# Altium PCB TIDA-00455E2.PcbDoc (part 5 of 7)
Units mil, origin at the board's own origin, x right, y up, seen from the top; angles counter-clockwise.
Board outline 6693 x 6693.1 mil, 8 copper layers (Layer 1 - Top Layer, Layer 2 - GND, Layer 3 - Sensitive, Layer 4 - GND, Layer 5 - PWR, Layer 6 - Signal, Layer 7 - GND, Layer 8 - Bottom Layer), stack 63.122 mil thick; 537 components, 407 nets, 1686 pads, 1249 vias.
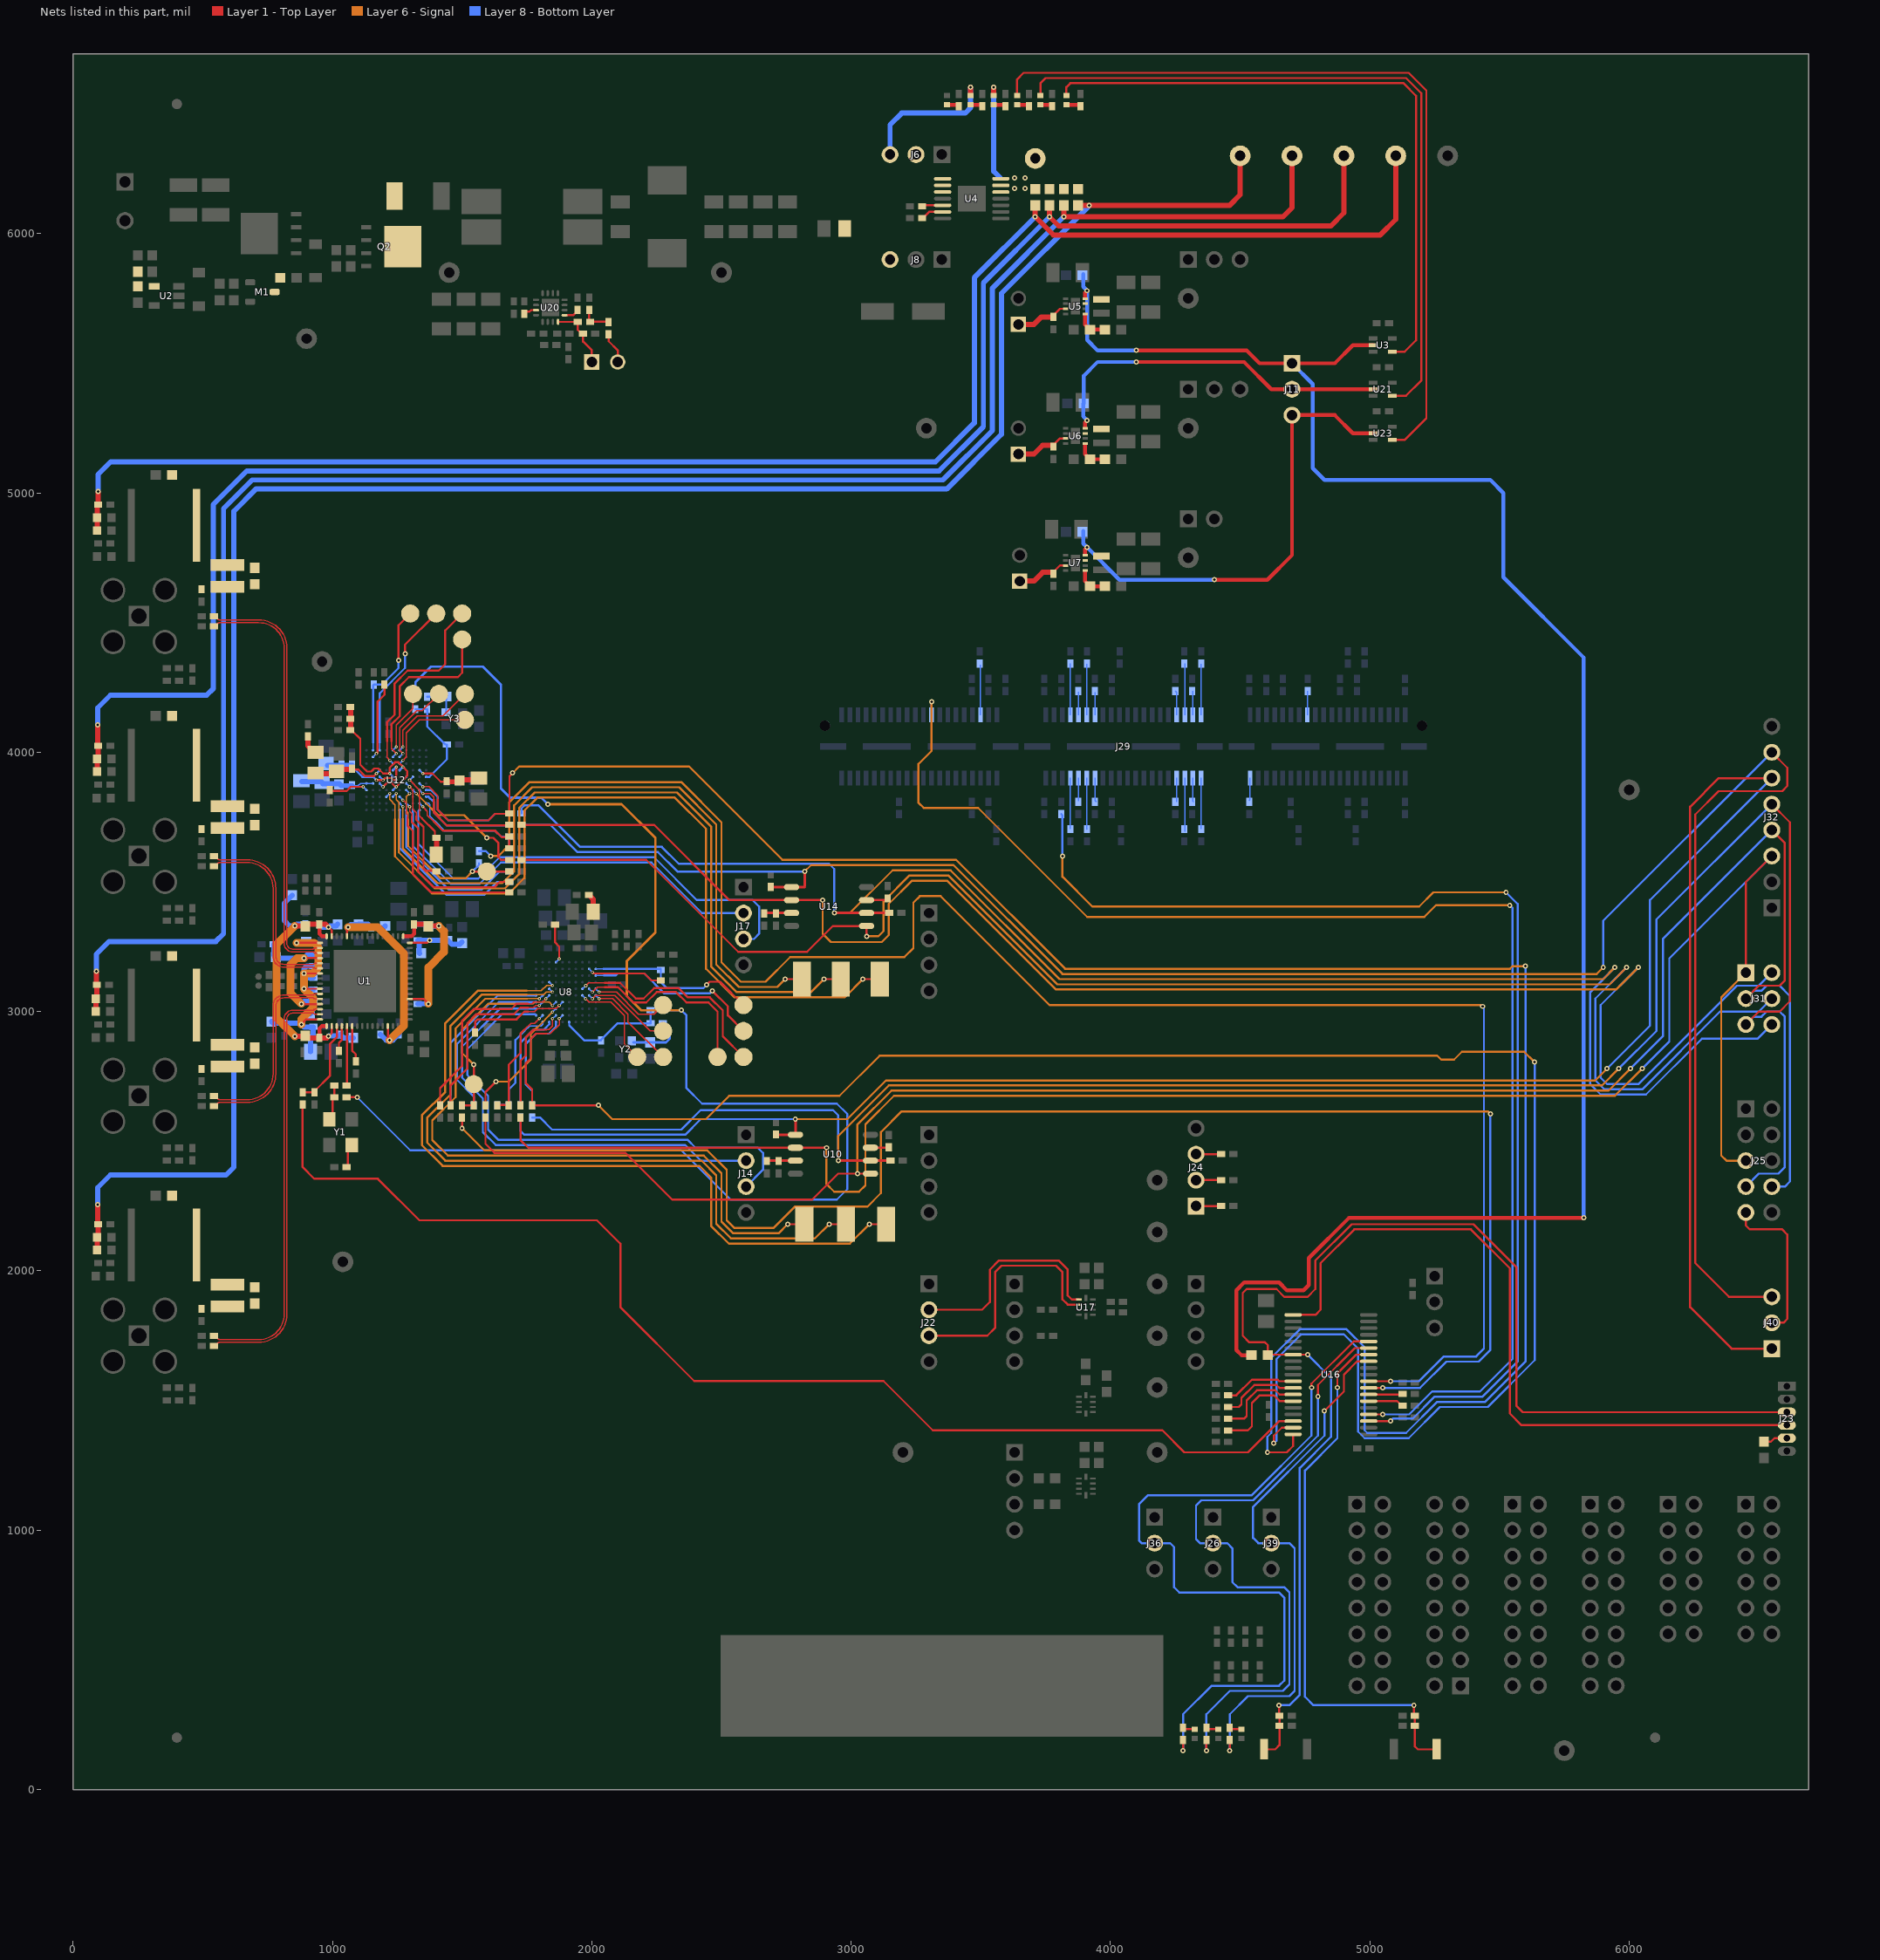
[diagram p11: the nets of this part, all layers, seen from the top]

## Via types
v1: diameter 20, hole 10, Layer 1 - Top Layer to Layer 8 - Bottom Layer, tented both sides, 1063 vias
v2: diameter 12, hole 6, Layer 1 - Top Layer to Layer 8 - Bottom Layer, tented bottom, 140 vias
v3: diameter 19.68, hole 7.87, Layer 1 - Top Layer to Layer 8 - Bottom Layer, 38 vias
v4: diameter 19.68, hole 7.87, Layer 1 - Top Layer to Layer 8 - Bottom Layer, tented top, 4 vias
v5: diameter 15.75, hole 7.87, Layer 1 - Top Layer to Layer 8 - Bottom Layer, 4 vias

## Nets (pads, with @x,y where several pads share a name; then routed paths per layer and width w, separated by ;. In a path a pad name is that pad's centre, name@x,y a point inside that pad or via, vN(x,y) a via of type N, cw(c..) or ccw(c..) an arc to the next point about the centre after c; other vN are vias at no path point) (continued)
NetC134_1: C134.1 R81.1 Y2.1 | length 215.9
  Layer 8 - Bottom Layer w10: Y2.1@2160.59,2881.5 C134.1@2225,2881.5 2286.5,2881.5 2300,2895 2300,2928.62 R81.1@2273.62,2955
NetC135_1: C135.1 C136.1 C137.1 L34.1 U12.F9 U12.F10 | length 285.8
  Layer 8 - Bottom Layer w5: C135.1@1076.24,3871.12 1098.86,3871.12 1107.44,3879.7 U12.F10@1131.08,3879.7 U12.F9@1156.67,3879.7
  Layer 8 - Bottom Layer w20: L34.1@881.24,3887.5 954.7,3887.5 963.21,3879 1026.24,3879 1034.11,3871.12 C135.1@1076.24,3871.12
NetC138_2: C138.2 C139.2 C142.2 U12.D6 U12.E8 U12.E9 U12.E10 U12.F6 | length 403.3
  Layer 1 - Top Layer w8: v2(1169.47,3892.5) v2(1195.06,3892.5) 1203.06,3900.5 1229.24,3900.5 1237.24,3892.5 v2(1246.24,3892.5) v2(1246.24,3943.68)
  Layer 8 - Bottom Layer w8: C142.2@1076.24,3948.88 1076.24,3943.76 1114.7,3905.3 U12.E10@1131.08,3905.3 U12.E9@1156.67,3905.3 v2(1169.47,3892.5) ; U12.E8@1182.26,3905.3 v2(1195.06,3892.5) ; U12.F6@1233.44,3879.7 v2(1246.24,3892.5) ; U12.D6@1233.44,3930.89 v2(1246.24,3943.68)
  Layer 8 - Bottom Layer w20: C139.2@981.4,3948.88 C142.2@1076.24,3948.88
NetC140_2: C140.2 C141.2 C162.2 U12.D5 U12.E4 U12.E6 U12.F8 U12.G6 | length 716.3
  Layer 1 - Top Layer w8: C162.2@1073.5,4082.5 1076.24,4082.5 1107.24,4051.5 1107.24,3951.5 1133.24,3925.5 1149.24,3925.5 1161.24,3937.5 1176.24,3937.5 1195.65,3918.09 v2(1220.65,3918.09) 1220.65,3940.65 1241.5,3961.5 1254.01,3961.5 v2(1271.83,3943.68) 1288.24,3927.27 1288.24,3908.91 v2(1271.83,3892.5) v2(1246.24,3866.91) 1242.83,3866.91 1226.24,3883.5 1211.65,3883.5 v2(1195.06,3866.91)
  Layer 1 - Top Layer w20: C162.2@1069.86,4086.14 C141.2@1069.86,4172.5
  Layer 8 - Bottom Layer w8: U12.F8@1182.26,3879.7 v2(1195.06,3866.91) ; v2(1220.65,3918.09) U12.E6@1233.44,3905.3 ; U12.G6@1233.44,3854.11 v2(1246.24,3866.91) ; U12.D5@1259.04,3930.89 v2(1271.83,3943.68) ; v2(1271.83,3892.5) U12.E4@1284.63,3905.3
NetC143_2: C143.2 C144.2 L35.1 U12.D8 | length 273.4
  Layer 1 - Top Layer w8: C144.2@1076.24,3933.88 1099.86,3933.88 1126.24,3907.5 1158.88,3907.5 v2(1169.47,3918.09)
  Layer 1 - Top Layer w20: L35.1@936.24,3917.5 1009.7,3917.5 1026.08,3933.88 C144.2@1076.24,3933.88
  Layer 8 - Bottom Layer w8: v2(1169.47,3918.09) U12.D8@1182.26,3930.89
NetC149_1: C149.1 L36.1 U12.E3 | length 336.7
  Layer 1 - Top Layer w5: v2(1297.42,3892.5) 1335.81,3854.11 1335.81,3754.19 1345,3745
  Layer 1 - Top Layer w8: 1345,3745 1395,3695 1395,3680.12 1402.62,3672.5 C149.1@1396.24,3672.5
  Layer 1 - Top Layer w20: L36.1@1401.24,3622.5 C149.1@1401.24,3671.12
  Layer 8 - Bottom Layer w5: v2(1297.42,3892.5) U12.E3@1310.22,3905.3
NetC150_1: C150.1 C153.2 R139.2 U12.D2 | length 250.8
  Layer 1 - Top Layer w8: v2(1348.6,3918.09) 1385.65,3918.09 1417.62,3886.12 C150.1@1441.24,3886.12
  Layer 1 - Top Layer w20: C150.1@1441.24,3886.12 1483.37,3886.12 1491.24,3894 1552.74,3894 R139.2@1561.24,3902.5
  Layer 8 - Bottom Layer w5: U12.D2@1335.81,3930.89 v2(1348.6,3918.09)
NetC154_1: C154.1 R111.1 Y3.1 | length 134.9
  Layer 8 - Bottom Layer w8: R111.1@1365,4213.62 1437.13,4213.62 C154.1@1438.5,4215 1438.5,4155.59 Y3.1@1437.52,4154.61
NetD4_1: D4.1 R168.1 | length 47.4
  Layer 1 - Top Layer w8: R168.1@4280,238.62 4285.91,232.72 D4.1@4325,232.72
NetD5_1: D5.1 R173.1 | length 47.4
  Layer 1 - Top Layer w8: R173.1@4370,238.62 4375.91,232.72 D5.1@4415,232.72
NetD6_2: D6.2 R50.2 | length 39.1
  Layer 1 - Top Layer w15: D6.2@3370,6497.28 R50.2@3409.09,6497.28
NetD7_1: D7.1 R125.2 | length 47.4
  Layer 1 - Top Layer w15: D7.1@3460,6497.28 3499.09,6497.28 R125.2@3505,6491.38
NetD8_2: D8.2 R127.1 | length 47.4
  Layer 1 - Top Layer w15: D8.2@3550,6497.28 3589.09,6497.28 R127.1@3595,6491.38
NetD9_1: D9.1 U3.4 | length 2459
  Layer 1 - Top Layer w8: D9.1@3830,6532.72 3830,6565 3845,6580 5130,6580 5178,6532 5178,5588 5134.41,5544.41 U3.4@5087.4,5544.41
NetD9_2: D9.2 R130.1 | length 57.4
  Layer 1 - Top Layer w15: D9.2@3830,6497.28 3879.09,6497.28 R130.1@3885,6491.38
NetD10_1: D10.1 U21.4 | length 2791.5
  Layer 1 - Top Layer w8: D10.1@3730,6532.72 3730,6580 3750,6600 5140,6600 5198,6542 5198,5433 5139.41,5374.41 U21.4@5087.4,5374.41
NetD10_2: D10.2 R131.2 | length 47.4
  Layer 1 - Top Layer w15: D10.2@3730,6497.28 3769.09,6497.28 R131.2@3775,6491.38
NetD11_1: D11.1 R132.2 | length 47.4
  Layer 1 - Top Layer w15: D11.1@3640,6497.28 3679.09,6497.28 R132.2@3685,6491.38
NetD11_2: D11.2 U23.4 | length 3108
  Layer 1 - Top Layer w8: D11.2@3640,6532.72 3640,6595 3665,6620 5150,6620 5218,6552 5218,5288 5134.41,5204.41 U23.4@5087.4,5204.41
NetD12_2: D12.2 R118.1 | length 47.4
  Layer 1 - Top Layer w8: R118.1@4460,238.62 4465.91,232.72 D12.2@4505,232.72
NetJ6_2: J6.2 U4.8 U4.9 U4.10
NetJ9_1: J9.1 R129.2 U5.3 | length 206.3
  Layer 1 - Top Layer w8: R129.2@3780,5683.62 3780,5685 3805.16,5710.16 U5.3@3827.6,5710.16
  Layer 1 - Top Layer w20: J9.1@3645,5650 3705,5650 3733.62,5678.62 R129.2@3780,5678.62
NetJ13_1: J13.1 R30.1 R31.1 U20.8 | length 257.8
  Layer 1 - Top Layer w8: U20.8@1869.53,5659.88 1946.26,5659.88 R30.1@1946.38,5660 1946.38,5628.62 1960,5615 R31.1@1966.38,5615 1966.38,5583.62 2000,5550 J13.1@2000,5505
NetJ13_2: J13.2 R117.1 | length 120.9
  Layer 1 - Top Layer w8: R117.1@2065,5611.38 2065,5585 2100,5550 J13.2@2100,5505
NetJ14_2: J14.2 U8.K3 | length 1769
  Layer 8 - Bottom Layer w8: U8.K3@1784.84,3011.02 1646.02,3011.02 1500,2865 1500,2745 1580,2665 1580,2535 1630,2485 2360,2485 2420,2425 J14.2@2595,2425
NetJ14_3: J14.3 U8.K2 | length 1920
  Layer 8 - Bottom Layer w8: U8.K2@1784.84,2985.43 1780.28,2990 1655,2990 1520,2855 1520,2755 1600,2675 1600,2545 1640,2505 2370,2505 2400,2475 2640,2475 2660,2455 2660,2390 J14.3@2595,2325
NetJ15_1: J15.1 R204.2 U7.3 | length 208.3
  Layer 1 - Top Layer w8: R204.2@3780,4693.62 3780,4695 3805.16,4720.16 U7.3@3827.6,4720.16
  Layer 1 - Top Layer w20: J15.1@3645,4660 J15.1@3650,4660 3705,4660 3738.62,4693.62 R204.2@3780,4693.62
NetJ17_2: J17.2 U12.K3 | length 1589
  Layer 8 - Bottom Layer w8: U12.K3@1310.22,3777.34 1310.22,3638.52 1456.24,3492.5 1567.5,3492.5 1650,3575 2230,3575 2425,3380 J17.2@2585,3380
NetJ17_3: J17.3 U12.K2 | length 1787.6
  Layer 8 - Bottom Layer w8: U12.K2@1335.81,3777.34 1331.24,3772.78 1331.24,3647.5 1466.24,3512.5 1562.5,3512.5 1645,3595 2240,3595 2405,3430 2620,3430 2645,3405 2645,3300 2625,3280 J17.3@2585,3280
NetJ22_2: J22.2 U17.1 | length 851.3
  Layer 1 - Top Layer w8: J22.2@3300,1850 3505,1850 3535,1880 3535,2005 3570,2040 3800,2040 3835,2005 3835,1905 3850.47,1889.53 U17.1@3878.43,1889.53
NetJ22_3: J22.3 U17.2 | length 939.9
  Layer 1 - Top Layer w8: J22.3@3300,1750 3525,1750 3555,1780 3555,1995 3580,2020 3790,2020 3815,1995 3815,1890 3835.16,1869.84 U17.2@3878.43,1869.84
NetJ23_5: J23.5 R142.1 | length 95.6
  Layer 1 - Top Layer w8: R142.1@6520,1341.5 6546.5,1341.5 6560,1355 J23.5@6608,1355 J23.5@6610,1355
NetJ24_1: J24.1 R143.2 | length 96.4
  Layer 1 - Top Layer w8: J24.1@4330,2250 R143.2@4426.38,2250
NetJ24_2: J24.2 R145.2 | length 96.4
  Layer 1 - Top Layer w8: J24.2@4330,2350 R145.2@4426.38,2350
NetJ24_3: J24.3 R147.2 | length 96.4
  Layer 1 - Top Layer w8: J24.3@4330,2450 R147.2@4426.38,2450
NetJ25_9: J25.9 J40.2 | length 615.7
  Layer 1 - Top Layer w8: J25.9@6450,2225 6450,2175 6465,2160 6590,2160 6610,2140 6610,1815 6595,1800 J40.2@6550,1800
NetJ30_1: J30.1 R201.2 U6.3 | length 208.3
  Layer 1 - Top Layer w8: R201.2@3780,5183.62 3780,5185 3805.16,5210.16 U6.3@3827.6,5210.16
  Layer 1 - Top Layer w20: J30.1@3645,5150 3705,5150 3738.62,5183.62 R201.2@3780,5183.62
NetL3_1: L3.1 L7.2 R1.1
NetL3_2: L3.2 L4.1 R1.2 R2.1
NetL5_1: L5.1 L8.2 R3.1
NetL5_2: L5.2 L6.1 R3.2 R4.1
NetL11_1: L11.1 L15.2 R9.1
NetL11_2: L11.2 L12.1 R9.2 R10.1
NetL13_1: L13.1 L16.2 R11.1
NetL13_2: L13.2 L14.1 R11.2 R12.1
NetL18_1: L18.1 U5.7
NetL19_1: L19.1 U6.7
NetL20_1: L20.1 U7.7
NetL32_2: L32.2 R78.2 | length 71.8
  Layer 1 - Top Layer w20: R78.2@1988.62,3450 2005,3433.62 L32.2@2005,3385
NetL35_2: L35.2 R108.2 | length 76.7
  Layer 1 - Top Layer w20: R108.2@905,4061.38 905,4025 930,4000 L35.2@935,4000
NetM1_3: M1.3 R19.1
NetQ2_5: Q2.5 R17.1
NetR21_1: R21.1 R23.2 U2.4
NetR26_2: R26.2 U20.3 | length 50.6
  Layer 1 - Top Layer w8: R26.2@1740,5691.38 1747.62,5699 1760,5699 1766.16,5705.16 U20.3@1784.88,5705.16
NetR28_2: R28.2 U20.9 | length 61.1
  Layer 1 - Top Layer w8: U20.9@1895.12,5685.47 1928.47,5685.47 1945,5702 R28.2@1945,5706.38
NetR29_2: R29.2 R30.2 R117.2 | length 119.8
  Layer 1 - Top Layer w8: R29.2@1990,5706.38 1990,5663.62 R30.2@1993.62,5660 2063.62,5660 R117.2@2065,5658.62
NetR37_1: R37.1 R38.2 U5.5 | length 121.9
  Layer 1 - Top Layer w15: U5.5@3902.4,5687 3902.4,5649.09 R38.2@3921.5,5630 R37.1@3978.5,5630
NetR40_1: R40.1 R41.2 U6.5 | length 121.9
  Layer 1 - Top Layer w15: U6.5@3902.4,5187 3902.4,5149.09 R41.2@3921.5,5130 R40.1@3978.5,5130
NetR43_1: R43.1 R44.2 U7.5 | length 121.9
  Layer 1 - Top Layer w15: U7.5@3902.4,4697 3902.4,4659.09 R44.2@3921.5,4640 R43.1@3978.5,4640
NetR45_2: R45.2 Y1.1 | length 93.2
  Layer 1 - Top Layer w8: R45.2@1054.82,2400 1060,2405.18 1060,2470.49 Y1.1@1074.51,2485
NetR46_1: R46.1 R47.2 Y1.3 | length 138.2
  Layer 1 - Top Layer w8: Y1.3@987.89,2585 1000,2597.11 1000,2662.42 R46.1@1007.58,2670 R47.2@1007.58,2715
NetR47_1: R47.1 U1.5 | length 229.8
  Layer 1 - Top Layer w8: R47.1@1054.82,2715 1056.1,2716.28 U1.5@1056.1,2944.27
NetR52_1: R52.1 U1.6 | length 141.5
  Layer 1 - Top Layer w8: U1.6@1075.79,2944.27 1075.79,2849.21 1090,2835 R52.1@1090,2808.62
NetR54_2: R54.2 U1.4 | length 100.4
  Layer 1 - Top Layer w8: R54.2@1025,2848.62 1025,2880 1036.42,2891.42 U1.4@1036.42,2944.27
NetR58_1: R58.1 TP37.1 U8.A9 | length 673.6
  Layer 1 - Top Layer w8: v1(2442.5,3102.5) 2455,3115 2495,3115 TP37.1@2585,3025
  Layer 8 - Bottom Layer w5: U8.A9@2015.16,3164.57 2045,3164.57
  Layer 8 - Bottom Layer w8: 2045,3164.57 R58.1@2266.38,3164.57 ; R58.1@2266.38,3160 2266.38,3113.62 2290,3090 2430,3090 v1(2442.5,3102.5)
NetR60_1: R60.1 R62.2 U10.3 | length 110.3
  Layer 1 - Top Layer w10: R62.2@2675,2425 U10.3@2785.31,2425
NetR61_2: R61.2 U10.7 | length 70.3
  Layer 1 - Top Layer w10: U10.7@3074.68,2475 R61.2@3145,2475
NetR65_1: R65.1 U8.J4 | length 669.6
  Layer 1 - Top Layer w5: 1755,3015 1775,3015 1783.82,3023.82 v2(1797.64,3023.82)
  Layer 1 - Top Layer w8: R65.1@1460,2638.62 1455,2643.62 1455,2715 1520,2780 1520,2955 1555,2990 1700,2990 1725,3015 1755,3015
  Layer 8 - Bottom Layer w5: v2(1797.64,3023.82) U8.J4@1810.43,3036.61
NetR66_1: R66.1 U8.H5 | length 739.9
  Layer 1 - Top Layer w5: 1755,3030 1770,3030 1776.61,3036.61 1810.43,3036.61 v2(1823.23,3049.41)
  Layer 1 - Top Layer w8: R66.1@1420,2638.62 1415,2643.62 1415,2705 1500,2790 1500,2965 1545,3010 1690,3010 1710,3030 1755,3030
  Layer 8 - Bottom Layer w5: v2(1823.23,3049.41) U8.H5@1836.02,3062.2
NetR67_1: R67.1 U8.K5 | length 648.7
  Layer 8 - Bottom Layer w8: R67.1@1455,2636.65 R67.1@1455,2638.62 1455,2880 1637.2,3062.2 U8.K5@1784.84,3062.2
NetR69_2: R69.2 U8.G2 | length 438.5
  Layer 1 - Top Layer w5: 1825,2930 1835,2930 1848.82,2943.82 v2(1848.82,2972.64)
  Layer 1 - Top Layer w8: R69.2@1725,2638.62 1725,2810 1745,2830 1745,2900 1775,2930 1825,2930
  Layer 8 - Bottom Layer w5: v2(1848.82,2972.64) U8.G2@1861.61,2985.43
NetR70_2: R70.2 U8.G3 | length 514.2
  Layer 1 - Top Layer w8: R70.2@1590,2638.62 1590,2690 v1(1630,2730)
  Layer 6 - Signal w5: 1790.59,2940 v2(1848.82,2998.23)
  Layer 6 - Signal w8: v1(1630,2730) 1680,2730 1765,2815 1765,2914.41 1790.59,2940
  Layer 8 - Bottom Layer w5: v2(1848.82,2998.23) U8.G3@1861.61,3011.02
NetR71_2: R71.2 U8.G1 | length 409.2
  Layer 8 - Bottom Layer w8: R71.2@1770,2638.62 1770,2695 1745,2720 1745,2875 1785,2915 1835,2915 1861.61,2941.61 U8.G1@1861.61,2959.84
NetR72_1: R72.1 U8.B9 | length 295.3
  Layer 1 - Top Layer w8: v2(2002.36,3151.77) 2007.13,3147 2203,3147 2230,3120 R72.1@2266.38,3120
  Layer 8 - Bottom Layer w5: U8.B9@1989.57,3164.57 v2(2002.36,3151.77)
NetR73_2: R73.2 U8.H1 | length 390.6
  Layer 8 - Bottom Layer w8: R73.2@1725,2638.62 1725,2880 1775,2930 1815,2930 1836.02,2951.02 U8.H1@1836.02,2959.84
NetR74_1: R74.1 U12.B9 | length 295.3
  Layer 1 - Top Layer w8: v2(1169.47,3994.86) 1174.24,3999.63 1174.24,4195.5 1201.24,4222.5 R74.1@1201.24,4258.88
  Layer 8 - Bottom Layer w5: U12.B9@1156.67,3982.07 v2(1169.47,3994.86)
NetR75_2: R75.2 U8.K4 | length 635.1
  Layer 8 - Bottom Layer w8: R75.2@1545,2638.62 1545,2672.38 1480,2737.38 1480,2875 1641.61,3036.61 U8.K4@1784.84,3036.61
NetR76_2: R76.2 U8.G10 | length 156.7
  Layer 1 - Top Layer w8: R76.2@1858.62,3335 1858.62,3266.38 1874.41,3250.59 v2(1874.41,3202.95)
  Layer 8 - Bottom Layer w5: U8.G10@1861.61,3190.16 v2(1874.41,3202.95)
NetR77_1: R77.1 U8.F4 | length 410.3
  Layer 1 - Top Layer w5: 1755,3000 1780,3000 1791.02,3011.02 1861.61,3011.02 v2(1874.41,3023.82)
  Layer 1 - Top Layer w8: R77.1@1550,2918.62 1550,2960 1560,2970 1710,2970 1740,3000 1755,3000
  Layer 8 - Bottom Layer w5: v2(1874.41,3023.82) U8.F4@1887.2,3036.61
NetR88_1: R88.1 TP47.1 U12.A9 | length 601.2
  Layer 1 - Top Layer w8: v1(1255,4355) 1255,4490 TP47.1@1300,4535
  Layer 8 - Bottom Layer w5: U12.A9@1156.67,4007.66 1156.67,4037.5
  Layer 8 - Bottom Layer w8: 1156.67,4037.5 R88.1@1156.67,4258.88 ; R88.1@1160,4261.38 1191.38,4261.38 1255,4325 v1(1255,4355)
NetR90_1: R90.1 R92.2 U14.3 | length 105.3
  Layer 1 - Top Layer w10: R92.2@2665,3380 U14.3@2770.32,3380
NetR91_2: R91.2 U14.7 | length 83
  Layer 1 - Top Layer w8: U14.7@3059.69,3430 3133.62,3430 R91.2@3140,3436.38
NetR95_1: R95.1 U12.J4 | length 666.2
  Layer 1 - Top Layer w5: v2(1297.42,3790.14) 1297.42,3771.58 1306,3763 1306,3752
  Layer 1 - Top Layer w8: 1306,3752 1306,3731 1330,3707 1330,3540 1390,3480 1625,3480 1645,3500 R95.1@1681.38,3500
  Layer 8 - Bottom Layer w5: U12.J4@1284.63,3802.93 v2(1297.42,3790.14)
NetR96_1: R96.1 U12.H5 | length 720
  Layer 1 - Top Layer w5: v2(1271.83,3815.73) 1284.63,3802.93 1284.63,3763.37 1289,3759 1289,3750
  Layer 1 - Top Layer w8: 1289,3750 1289,3718 1310,3697 1310,3530 1380,3460 R96.1@1681.38,3460
  Layer 8 - Bottom Layer w5: U12.H5@1259.04,3828.52 v2(1271.83,3815.73)
NetR97_1: R97.1 U12.K5 | length 664.4
  Layer 8 - Bottom Layer w8: U12.K5@1259.04,3777.34 1259.04,3630.96 1440,3450 1585,3450 1635,3500 R97.1@1681.38,3500
NetR99_2: R99.2 U12.G2 | length 438.5
  Layer 1 - Top Layer w5: v2(1348.6,3841.32) 1377.42,3841.32 1391.24,3827.5 1391.24,3817.5
  Layer 1 - Top Layer w8: 1391.24,3817.5 1391.24,3767.5 1441.24,3717.5 R99.2@1682.62,3717.5
  Layer 8 - Bottom Layer w5: U12.G2@1335.81,3854.11 v2(1348.6,3841.32)
NetR100_2: R100.2 U12.G3 | length 514.9
  Layer 1 - Top Layer w8: v1(1595,3670) 1620,3670 1640,3650 1640,3595 1650,3585 R100.2@1681.38,3585
  Layer 6 - Signal w5: v2(1323.01,3841.32) 1381.24,3783.09
  Layer 6 - Signal w8: 1381.24,3783.09 1406.83,3757.5 1507.5,3757.5 v1(1595,3670)
  Layer 8 - Bottom Layer w5: U12.G3@1310.22,3854.11 v2(1323.01,3841.32)
NetR101_2: R101.2 U12.G1 | length 409.2
  Layer 8 - Bottom Layer w8: U12.G1@1361.4,3854.11 1379.63,3854.11 1406.24,3827.5 1406.24,3777.5 1446.24,3737.5 1601.24,3737.5 1626.24,3762.5 R101.2@1682.62,3762.5
NetR103_2: R103.2 U12.H1 | length 390.6
  Layer 8 - Bottom Layer w8: U12.H1@1361.4,3828.52 1370.22,3828.52 1391.24,3807.5 1391.24,3767.5 1441.24,3717.5 R103.2@1682.62,3717.5
NetR105_2: R105.2 U12.K4 | length 637
  Layer 8 - Bottom Layer w8: U12.K4@1284.63,3777.34 1284.63,3634.11 1448.74,3470 1575,3470 1645,3540 R105.2@1681.38,3540
NetR106_2: R106.2 U12.G10 | length 150.4
  Layer 1 - Top Layer w8: R106.2@992.5,3851.12 1054.86,3851.12 1070.65,3866.91 v2(1118.29,3866.91)
  Layer 8 - Bottom Layer w5: v2(1118.29,3866.91) U12.G10@1131.08,3854.11
NetR107_1: R107.1 U12.F4 | length 410.3
  Layer 1 - Top Layer w5: v2(1297.42,3866.91) 1310.22,3854.11 1310.22,3779.78 1323,3767 1323,3754
  Layer 1 - Top Layer w8: 1323,3754 1323,3740 1351.24,3711.76 1351.24,3552.5 1361.24,3542.5 R107.1@1402.62,3542.5
  Layer 8 - Bottom Layer w5: U12.F4@1284.63,3879.7 v2(1297.42,3866.91)
NetR126_2: R126.2 U16.12 | length 305.2
  Layer 1 - Top Layer w8: R126.2@4453.62,1475 4495,1475 4505,1485 4505,1510 4555,1560 4640,1560 4651.18,1548.82 U16.12@4704.33,1548.82
NetR128_2: R128.2 U16.13 | length 338.4
  Layer 1 - Top Layer w8: R128.2@4453.62,1430 4515,1430 4525,1440 4525,1500 4565,1540 4635,1540 4651.77,1523.23 U16.13@4704.33,1523.23
NetR134_2: R134.2 R159.1 TP41.1 U8.G4 | length 771.4
  Layer 1 - Top Layer w8: R159.1@1500,2638.62 R134.2@1545,2638.62 TP41.1@1545,2720 v1(1545,2795)
  Layer 6 - Signal w5: 1750,3030 1775,3030 1781.61,3036.61 1836.02,3036.61 v2(1848.82,3023.82)
  Layer 6 - Signal w8: v1(1545,2795) 1500,2840 1500,2930 1600,3030 1750,3030
  Layer 8 - Bottom Layer w5: v2(1848.82,3023.82) U8.G4@1861.61,3036.61
NetR138_2: R138.2 R162.1 TP42.1 U12.G4 | length 722.2
  Layer 1 - Top Layer w8: v1(1540,3540) TP42.1@1595,3540 R138.2@1681.38,3540
  Layer 6 - Signal w5: 1291.24,3742.5 1291.24,3767.5 1284.63,3774.11 1284.63,3828.52 v2(1297.42,3841.32)
  Layer 6 - Signal w8: 1291.24,3742.5 1291.24,3638.76 1415,3515 1515,3515 v1(1540,3540)
  Layer 8 - Bottom Layer w5: U12.G4@1284.63,3854.11 v2(1297.42,3841.32)
  Layer 8 - Bottom Layer w8: v1(1540,3540) 1565,3565 R162.1@1565,3571.38
NetR140_2: R140.2 U4.13 | length 89
  Layer 1 - Top Layer w8: R140.2@3273.62,6060 3277,6060 3300.82,6083.82 U4.13@3352.8,6083.82
NetR154_1: R154.1 R155.2 U1.3 | length 336.6
  Layer 1 - Top Layer w8: R154.1@885,2688.62 R155.2@930,2688.62 930,2692 990,2752 990,2875 1016.73,2901.73 U1.3@1016.73,2944.27
NetR163_2: R163.2 U16.11 | length 277.9
  Layer 1 - Top Layer w8: R163.2@4453.62,1520 4485,1520 4545,1580 4645,1580 4650.59,1574.41 U16.11@4704.33,1574.41
NetR164_2: R164.2 U16.14 | length 370.6
  Layer 1 - Top Layer w8: R164.2@4451.65,1385 R164.2@4453.62,1385 4530,1385 4545,1400 4545,1490 4575,1520 4630,1520 4652.36,1497.64 U16.14@4704.33,1497.64
NetR165_2: R165.2 U16.25 | length 138
  Layer 1 - Top Layer w8: U16.25@4995.67,1497.64 5105.36,1497.64 5123,1480 R165.2@5126.38,1480
NetR166_2: R166.2 U16.26 | length 131.4
  Layer 1 - Top Layer w8: U16.26@4995.67,1523.23 5124.61,1523.23 R166.2@5126.38,1525
NetR184_1: R184.1 U4.12 | length 81
  Layer 1 - Top Layer w8: R184.1@3273.62,6105 3278.03,6109.41 U4.12@3352.8,6109.41
NetTP18_1: TP18.1 U8.H7 | length 3087.3
  Layer 1 - Top Layer w8: v1(3070,2180) TP18.1@3135,2180
  Layer 6 - Signal w5: 1750,3080 1805,3080 1825.59,3100.59 v2(1848.82,3100.59)
  Layer 6 - Signal w8: 1750,3080 1560,3080 1435,2955 1435,2690 1345,2600 1345,2485 1425,2405 2415,2405 2460,2360 2460,2173.43 2528.43,2105 2995,2105 v1(3070,2180)
  Layer 8 - Bottom Layer w5: U8.H7@1836.02,3113.39 v2(1848.82,3100.59)
NetTP19_1: TP19.1 U8.H6 | length 2853.4
  Layer 1 - Top Layer w8: v1(2915,2180) TP19.1@2980,2180
  Layer 6 - Signal w5: 1750,3065 1815,3065 1825,3075 v2(1848.82,3075)
  Layer 6 - Signal w8: 1750,3065 1575,3065 1455,2945 1455,2680 1365,2590 1365,2495 1435,2425 2423.28,2425 2480,2368.28 2480,2181.72 2536.72,2125 2860,2125 v1(2915,2180)
  Layer 8 - Bottom Layer w5: U8.H6@1836.02,3087.8 v2(1848.82,3075)
NetTP20_1: TP20.1 U8.J5 | length 2563.3
  Layer 1 - Top Layer w8: v1(2755,2180) TP20.1@2820,2180
  Layer 6 - Signal w5: 1750.59,3049.41 v2(1797.64,3049.41)
  Layer 6 - Signal w8: 1750.59,3049.41 1589.41,3049.41 1475,2935 1475,2670 1385,2580 1385,2505 1445,2445 2431.57,2445 2500,2376.57 2500,2190 2545,2145 2720,2145 v1(2755,2180)
  Layer 8 - Bottom Layer w5: v2(1797.64,3049.41) U8.J5@1810.43,3062.2
NetTP21_1: TP21.1 U12.H7 | length 3167.2
  Layer 1 - Top Layer w8: v1(3045,3125) TP21.1@3110,3125
  Layer 6 - Signal w5: v2(1220.65,3841.32) 1220.65,3818.09 1241.24,3797.5 1241.24,3742.5
  Layer 6 - Signal w8: 1241.24,3742.5 1241.24,3598.76 1385,3455 1680,3455 1740,3515 1740,3775 1790,3825 2320,3825 2440,3705 2440,3165.15 2550.15,3055 2975,3055 v1(3045,3125)
  Layer 8 - Bottom Layer w5: U12.H7@1207.85,3828.52 v2(1220.65,3841.32)
NetTP22_1: TP22.1 U12.H6 | length 2969.6
  Layer 1 - Top Layer w8: v1(2895,3125) TP22.1@2960,3125
  Layer 6 - Signal w5: v2(1246.24,3841.32) 1246.24,3817.5 1256.24,3807.5 1256.24,3742.5
  Layer 6 - Signal w8: 1256.24,3742.5 1256.24,3613.76 1395,3475 1665,3475 1720,3530 1720,3785 1780,3845 2328.28,3845 2460,3713.28 2460,3173.43 2558.43,3075 2845,3075 v1(2895,3125)
  Layer 8 - Bottom Layer w5: U12.H6@1233.44,3828.52 v2(1246.24,3841.32)
NetTP23_1: TP23.1 U12.J5 | length 2723.6
  Layer 1 - Top Layer w8: v1(2745,3125) TP23.1@2810,3125
  Layer 6 - Signal w5: 1271.83,3743.09 v2(1271.83,3790.14)
  Layer 6 - Signal w8: 1271.83,3743.09 1271.83,3628.17 1405,3495 1655,3495 1700,3540 1700,3795 1770,3865 2336.57,3865 2480,3721.57 2480,3181.72 2566.72,3095 2715,3095 v1(2745,3125)
  Layer 8 - Bottom Layer w5: U12.J5@1259.04,3802.93 v2(1271.83,3790.14)
NetTP29_1: TP29.1 U12.A6 | length 249.3
  Layer 1 - Top Layer w5: v2(1246.24,4020.45) 1246.24,4104.33 1310.5,4168.59 TP29.1@1310.5,4225
  Layer 8 - Bottom Layer w5: U12.A6@1233.44,4007.66 v2(1246.24,4020.45)
NetTP30_1: TP30.1 U12.B5 | length 328.3
  Layer 1 - Top Layer w5: v2(1271.83,3994.86) 1259,4007.69 1259,4094 1325,4160 1345.5,4160 TP30.1@1410.5,4225
  Layer 8 - Bottom Layer w5: U12.B5@1259.04,3982.07 v2(1271.83,3994.86)
NetTP31_1: TP31.1 U12.A5 | length 378.9
  Layer 1 - Top Layer w5: v2(1271.83,4020.45) 1271.83,4084.33 1327.5,4140 1425.5,4140 TP31.1@1510.5,4225
  Layer 8 - Bottom Layer w5: U12.A5@1259.04,4007.66 v2(1271.83,4020.45)
NetTP32_1: TP32.1 U12.C5 | length 375.5
  Layer 1 - Top Layer w5: v2(1271.83,3969.27) 1284.7,3982.14 1284.7,4074.7 1335,4125 TP32.1@1510.5,4125
  Layer 8 - Bottom Layer w5: U12.C5@1259.04,3956.48 v2(1271.83,3969.27)
NetTP33_1: TP33.1 U8.A6 | length 314.8
  Layer 1 - Top Layer w5: v2(2027.95,3075) 2095,3075 2180,2990 2240,2990 TP33.1@2275,3025
  Layer 8 - Bottom Layer w5: U8.A6@2015.16,3087.8 v2(2027.95,3075)
NetTP34_1: TP34.1 U8.B5 | length 352.6
  Layer 1 - Top Layer w5: v2(2002.36,3049.41) 2014.86,3061.91 2088.09,3061.91 2225,2925 TP34.1@2275,2925
  Layer 8 - Bottom Layer w5: U8.B5@1989.57,3062.2 v2(2002.36,3049.41)
NetTP35_1: TP35.1 U8.A5 | length 375.7
  Layer 1 - Top Layer w5: v2(2027.95,3049.41) 2080.59,3049.41 2140,2990 2140,2960 TP35.1@2275,2825
  Layer 8 - Bottom Layer w5: U8.A5@2015.16,3062.2 v2(2027.95,3049.41)
NetTP36_1: TP36.1 U8.C5 | length 373.7
  Layer 1 - Top Layer w5: v2(1976.77,3049.41) 1989.27,3036.91 2073.09,3036.91 2125,2985 2125,2875 TP36.1@2175,2825
  Layer 8 - Bottom Layer w5: U8.C5@1963.98,3062.2 v2(1976.77,3049.41)
NetTP38_1: TP38.1 U8.A8 | length 693.9
  Layer 1 - Top Layer w8: v1(2465,3080) 2525,3020 2525,2985 TP38.1@2585,2925
  Layer 8 - Bottom Layer w5: U8.A8@2015.16,3138.98 2046.61,3138.98
  Layer 8 - Bottom Layer w8: 2046.61,3138.98 2091.98,3138.98 2100,3147 2203,3147 2280,3070 2455,3070 v1(2465,3080)
NetTP39_1: TP39.1 U8.B6 | length 755.7
  Layer 1 - Top Layer w5: v2(2002.36,3075) 2021.36,3094 2050.26,3094
  Layer 1 - Top Layer w8: 2050.26,3094 2101,3094 2160,3035 2210,3035 2250,3075 2325,3075 2365,3035 2450,3035 2485,3000 TP39.1@2485,2825
  Layer 8 - Bottom Layer w5: U8.B6@1989.57,3087.8 v2(2002.36,3075)
NetTP40_1: TP40.1 U8.C6 | length 841.1
  Layer 1 - Top Layer w5: v2(1976.8,3099.8) 1988,3111 2050,3111
  Layer 1 - Top Layer w8: 2050,3111 2109,3111 2170,3050 2200,3050 2240,3090 2335,3090 2370,3055 2455,3055 2505,3005 2505,2905 TP40.1@2585,2825
  Layer 8 - Bottom Layer w5: U8.C6@1964,3087 v2(1976.8,3099.8)
NetTP48_1: TP48.1 U12.A8 | length 617.5
  Layer 1 - Top Layer w8: v1(1280,4380) 1280,4415 TP48.1@1400,4535
  Layer 8 - Bottom Layer w5: U12.A8@1182.26,4007.66 1182.26,4037.5
  Layer 8 - Bottom Layer w8: 1182.26,4037.5 1182.26,4227.26 1280,4325 v1(1280,4380)
NetTP49_1: TP49.1 U12.B6 | length 689.6
  Layer 1 - Top Layer w5: 1227.24,4042.76 1227.24,4013.86 v2(1246.24,3994.86)
  Layer 1 - Top Layer w8: 1227.24,4042.76 1227.24,4107.24 1260,4140 1260,4255 1295,4290 1483.62,4290 1500,4306.38 TP49.1@1500,4435
  Layer 8 - Bottom Layer w5: U12.B6@1233.44,3982.07 v2(1246.24,3994.86)
NetTP50_1: TP50.1 U12.C6 | length 778.8
  Layer 1 - Top Layer w5: 1210.24,4042.5 1210.24,3980.5 v2(1221.44,3969.3)
  Layer 1 - Top Layer w8: 1210.24,4042.5 1210.24,4115.24 1240,4145 1240,4265 1290,4315 1410,4315 1435,4340 1435,4470 TP50.1@1500,4535
  Layer 8 - Bottom Layer w5: v2(1221.44,3969.3) U12.C6@1234.24,3956.5
NRESET_OV1: R159.2 U16.27 | length 6048.2
  Layer 1 - Top Layer w8: v1(1500,2550) R159.2@1500,2591.38 ; U16.27@4995.67,1548.82 v1(5050,1548.82)
  Layer 6 - Signal w8: v1(1500,2550) 1585,2465 2445,2465 2520,2390 2520,2195 2550,2165 2700,2165 2782.5,2247.5 3062.5,2247.5 3115,2300 3115,2535 3195,2615 5455,2615 v1(5465,2605)
  Layer 8 - Bottom Layer w8: v1(5050,1548.82) 5193.82,1548.82 5295,1650 5420,1650 5465,1695 v1(5465,2605)
NRESET_OV2: R162.2 U16.28 | length 6961.3
  Layer 1 - Top Layer w8: U16.28@4995.67,1574.41 v1(5080,1574.41)
  Layer 6 - Signal w8: v1(1610,3600) 1640,3600 1681.24,3641.24 1681.24,3806.24 1760,3885 2344.85,3885 2500,3729.85 2500,3190 2575,3115 2670,3115 2765,3210 3205,3210 3240,3245 3240,3420 3265,3445 3345,3445 3765,3025 5430,3025 v1(5435,3020)
  Layer 8 - Bottom Layer w8: R162.2@1565,3618.62 1591.38,3618.62 v1(1610,3600) ; v1(5080,1574.41) 5189.41,1574.41 5285,1670 5410,1670 5440,1700 5440,3015 v1(5435,3020)
NRESET_SOC: R214.2 U16.22 | length 4521.7
  Layer 1 - Top Layer w8: U16.22@4995.67,1420.87 v1(5080,1420.87)
  Layer 6 - Signal w8: v1(3815,3600) 3815,3520 3930,3405 5190,3405 5245,3460 v1(5525,3460)
  Layer 8 - Bottom Layer w8: R214.2@3810,3761.38 3815,3756.38 v1(3815,3600) ; v1(5080,1420.87) 5089.13,1430 5165,1430 5250,1515 5435,1515 5570,1650 5570,3415 v1(5525,3460)
PDB_UB960: R154.2 U16.17 | length 4709.9
  Layer 1 - Top Layer w8: R154.2@885,2641.38 885,2400 930,2355 1175,2355 1335,2195 2020,2195 2110,2105 2110,1860 2395,1575 3125,1575 3315,1385 4200,1385 4285,1300 4530,1300 4650.87,1420.87 U16.17@4704.33,1420.87
PG_1V1: J11.3 R42.2 U7.8 U23.2 | length 1862.6
  Layer 1 - Top Layer w15: U7.8@3902.4,4763 3902.4,4782.4 v1(3910,4790) ; v1(4400,4665) 4605,4665 4700,4760 J11.3@4700,5300 4865,5300 4935,5230 U23.2@5012.6,5230
  Layer 8 - Bottom Layer w15: R42.2@3895,4853.5 3895,4805 v1(3910,4790) 4035,4665 v1(4400,4665)
PG_1V8: J11.2 R39.2 U6.8 U21.2 | length 1388.1
  Layer 1 - Top Layer w15: U6.8@3902.4,5253 3902.4,5272.4 v1(3910,5280) ; v1(4100,5505) 4515,5505 4620,5400 J11.2@4700,5400 U21.2@5012.6,5400
  Layer 8 - Bottom Layer w15: R39.2@3895,5343.5 3895,5295 v1(3910,5280) ; R39.2@3896.5,5345 3896.5,5451.5 3950,5505 v1(4100,5505)
PG_3V3: J11.1 R36.1 R156.2 U3.2 U5.8 | length 7433.8
  Layer 1 - Top Layer w15: U5.8@3902.4,5753 3902.4,5772.4 v1(3910,5780) ; v1(4100,5550) 4525,5550 4575,5500 J11.1@4700,5500 4865,5500 4935,5570 U3.2@5012.6,5570 ; R156.2@4543.5,1675 4505,1675 4485,1695 4485,1925 4515,1955 4650,1955 4680,1925 4745,1925 4765,1945 4765,2050 4920,2205 v1(5825,2205)
  Layer 8 - Bottom Layer w15: R36.1@3895,5843.5 3895,5795 v1(3910,5780) 3910,5590 3950,5550 v1(4100,5550) ; J11.1@4700,5500 4780,5420 4780,5095 4825,5050 5465,5050 5515,5000 5515,4675 5825,4365 v1(5825,2205)
PWDN_OV1: R133.2 U8.F2 U16.18 | length 7581
  Layer 1 - Top Layer w5: 1825,2915 1840,2915 1874.41,2949.41 v2(1874.41,2972.64)
  Layer 1 - Top Layer w8: 1825,2915 1785,2915 1765,2895 1765,2820 1745,2800 1745,2725 1770,2700 R133.2@1770,2638.62 v1(2025,2638.62) ; v1(4630,1335) 4630,1365 4660.28,1395.28 U16.18@4704.33,1395.28
  Layer 6 - Signal w8: v1(2025,2638.62) 2078.62,2585 2440,2585 2530,2675 2955,2675 3110,2830 5260,2830 5275,2815 5325,2815 5355,2845 5595,2845 v1(5635,2805)
  Layer 8 - Bottom Layer w5: v2(1874.41,2972.64) U8.F2@1887.2,2985.43
  Layer 8 - Bottom Layer w8: v1(4630,1335) 4640,1345 4640,1660 4735,1755 4900,1755 4955,1700 4955,1380 4980,1355 5150,1355 5270,1475 5455,1475 5636.21,1656.21 5636.21,2803.79 v1(5635,2805)
PWDN_OV2: R137.2 U12.F2 U16.19 | length 8397.1
  Layer 1 - Top Layer w5: v2(1348.6,3866.91) 1371.83,3866.91 1406.24,3832.5 1406.24,3817.5
  Layer 1 - Top Layer w8: 1406.24,3817.5 1406.24,3777.5 1446.24,3737.5 1601.24,3737.5 1626.24,3762.5 1682.62,3762.5 1682.62,3907.62 v1(1695,3920) ; v1(4605,1300) 4680,1300 4704.33,1324.33 U16.19@4704.33,1369.69
  Layer 6 - Signal w8: v1(1695,3920) 1720,3945 2375,3945 2735,3585 3405,3585 3825,3165 5540,3165 5550,3175 v1(5600,3175)
  Layer 8 - Bottom Layer w5: U12.F2@1335.81,3879.7 v2(1348.6,3866.91)
  Layer 8 - Bottom Layer w8: v1(4605,1300) 4605,1360 4620,1375 4620,1665 4730,1775 4910,1775 4980,1705 4980,1385 4990,1375 5140,1375 5260,1495 5445,1495 5600,1650 v1(5600,3175)
RIN0_N: C11.2 U1.51 | length 1628.3
  Layer 1 - Top Layer w5: C11.2@543.62,4485 ccw(c543.62,4493.16) 549.39,4487.39 559,4497 cw(c565.64,4490.36) 565.64,4499.75 715.41,4499.75 cw(c715.41,4401.16) 814,4401.16 814,3262 ccw(c845.78,3262) 845.78,3230.22 924.17,3230.22 cw(c924.17,3223.39) 929,3228.22 ccw(c934.92,3234.14) 934.92,3225.77 U1.51@951.77,3225.77
RIN0_P: C9.1 U1.50 | length 1628.2
  Layer 1 - Top Layer w5: C9.1@543.62,4525 cw(c543.62,4516.84) 549.39,4522.61 559,4513 ccw(c565.64,4519.64) 565.64,4510.25 715.68,4510.25 cw(c715.68,4401.43) 824.5,4401.43 824.5,3262 ccw(c845.5,3262) 845.5,3241 924.17,3241 ccw(c924.17,3247.83) 929,3243 cw(c934.92,3237.08) 934.92,3245.45 U1.50@951.77,3245.45
RIN1_N: C12.2 U1.54 | length 757.2
  Layer 1 - Top Layer w5: C12.2@543.62,3560 ccw(c543.62,3568.16) 549.39,3562.39 559,3572 cw(c565.64,3565.36) 565.64,3574.75 671,3574.75 cw(c671,3474.75) 771,3474.75 771,3213.55 ccw(c813.39,3213.55) 813.39,3171.17 924.17,3171.17 cw(c924.17,3164.34) 929,3169.17 ccw(c934.92,3175.09) 934.92,3166.71 U1.54@951.77,3166.71
RIN1_P: C10.1 U1.53 | length 757
  Layer 1 - Top Layer w5: C10.1@543.62,3600 cw(c543.62,3591.84) 549.39,3597.61 559,3588 ccw(c565.64,3594.64) 565.64,3585.25 671,3585.25 cw(c671,3474.75) 781.5,3474.75 781.5,3213.62 ccw(c813.17,3213.62) 813.17,3181.94 924.17,3181.94 ccw(c924.17,3188.77) 929,3183.94 cw(c934.92,3178.02) 934.92,3186.4 U1.53@951.77,3186.4
RIN2_N: C25.2 U1.60 | length 757
  Layer 1 - Top Layer w5: C25.2@543.62,2635 ccw(c543.62,2643.16) 549.39,2637.39 559,2647 cw(c565.64,2640.36) 565.64,2649.75 671,2649.75 ccw(c671,2760.25) 781.5,2760.25 781.5,3021.38 cw(c813.17,3021.38) 813.17,3053.06 924.17,3053.06 cw(c924.17,3046.23) 929,3051.06 ccw(c934.92,3056.98) 934.92,3048.6 U1.60@951.77,3048.6
RIN2_P: C23.1 U1.59 | length 757.2
  Layer 1 - Top Layer w5: C23.1@543.62,2675 cw(c543.62,2666.84) 549.39,2672.61 559,2663 ccw(c565.64,2669.64) 565.64,2660.25 671,2660.25 ccw(c671,2760.25) 771,2760.25 771,3021.45 cw(c813.39,3021.45) 813.39,3063.83 924.17,3063.83 ccw(c924.17,3070.66) 929,3065.83 cw(c934.92,3059.91) 934.92,3068.29 U1.59@951.77,3068.29
RIN3_N: C26.2 U1.63 | length 1628.2
  Layer 1 - Top Layer w5: C26.2@543.62,1710 ccw(c543.62,1718.16) 549.39,1712.39 559,1722 cw(c565.64,1715.36) 565.64,1724.75 715.68,1724.75 ccw(c715.68,1833.57) 824.5,1833.57 824.5,2973 cw(c845.5,2973) 845.5,2994 924.17,2994 cw(c924.17,2987.17) 929,2992 ccw(c934.92,2997.92) 934.92,2989.55 U1.63@951.77,2989.55
RIN3_P: C24.1 U1.62 | length 1628.3
  Layer 1 - Top Layer w5: C24.1@543.62,1750 cw(c543.62,1741.84) 549.39,1747.61 559,1738 ccw(c565.64,1744.64) 565.64,1735.25 715.41,1735.25 ccw(c715.41,1833.83) 814,1833.83 814,2973 cw(c845.78,2973) 845.78,3004.78 924.17,3004.78 ccw(c924.17,3011.61) 929,3006.78 cw(c934.92,3000.86) 934.92,3009.23 U1.62@951.77,3009.23
RTS_SOC: J29.97 U16.23 | length 5339.1
  Layer 1 - Top Layer w8: U16.23@4995.67,1446.46 v1(5050,1446.46)
  Layer 6 - Signal w8: v1(3310.03,4194.69) 3310.03,4005.03 3260,3955 3260,3805 3280,3785 3490,3785 3910,3365 5210,3365 5255,3410 v1(5540,3410)
  Layer 8 - Bottom Layer w8: J29.97@3310.03,4143.8 v1(3310.03,4194.69) ; v1(5050,1446.46) 5151.46,1446.46 5240,1535 5425,1535 5550,1660 5550,3400 v1(5540,3410)
SBWTCK1: J23.4 U16.1 | length 2786.4
  Layer 1 - Top Layer w8: U16.1@4704.33,1830.32 4790.31,1830.32 4810,1850 4810,2030 4940,2160 5390,2160 5540,2010 5540,1450 5585,1405 J23.4@6608,1405
SCCBID0_OV1: R83.1 R85.2 U8.J2 | length 455.2
  Layer 1 - Top Layer w5: 1740,2930 1765,2955 1780,2955 v2(1797.64,2972.64)
  Layer 1 - Top Layer w8: R83.1@1635,2638.62 1636.38,2640 R85.2@1680,2640 ; R85.2@1680,2638.62 R85.2@1680,2640 ; 1740,2930 1725,2915 1725,2840 1680,2795 R85.2@1680,2640
  Layer 8 - Bottom Layer w5: v2(1797.64,2972.64) U8.J2@1810.43,2985.43
SCCBID0_OV2: R113.1 R115.2 U12.J2 | length 455.2
  Layer 1 - Top Layer w5: v2(1348.6,3790.14) 1366.24,3772.5 1366.24,3757.5 1391.24,3732.5
  Layer 1 - Top Layer w8: 1391.24,3732.5 1426.24,3697.5 1627.5,3697.5 1652.5,3672.5 R115.2@1681.24,3672.5 ; R113.1@1682.62,3627.5 1681.24,3628.88 R115.2@1681.24,3672.5 ; R115.2@1682.62,3672.5 R115.2@1681.24,3672.5
  Layer 8 - Bottom Layer w5: U12.J2@1335.81,3802.93 v2(1348.6,3790.14)
SCCBID1_OV1: R82.1 R84.2 U8.J1 | length 445.2
  Layer 8 - Bottom Layer w5: 1740,2925 1760,2945 1805,2945 1810.43,2950.43 U8.J1@1810.43,2959.84
  Layer 8 - Bottom Layer w8: R82.1@1636.38,2640 R84.2@1680,2640 ; R84.2@1680,2638.62 R84.2@1680,2640 ; 1740,2925 1705,2890 1705,2725 1680,2700 R84.2@1680,2640
SCCBID1_OV2: R112.1 R114.2 U12.J1 | length 445.2
  Layer 8 - Bottom Layer w5: U12.J1@1361.4,3802.93 1370.81,3802.93 1376.24,3797.5 1376.24,3752.5 1396.24,3732.5
  Layer 8 - Bottom Layer w8: 1396.24,3732.5 1431.24,3697.5 1627.5,3697.5 1650,3675 1678.74,3675 R114.2@1681.24,3672.5 ; R112.1@1681.24,3628.88 R114.2@1681.24,3672.5 ; R114.2@1682.62,3672.5 R114.2@1681.24,3672.5
SPARE1_UC: J36.2 R168.2 U16.34 | length 3090.1
  Layer 1 - Top Layer w8: v1(4280,150) R168.2@4280,191.38 ; v1(4775,1550) 4775,1565 4937.95,1727.95 U16.34@4995.67,1727.95
  Layer 8 - Bottom Layer w8: v1(4280,150) 4280,290 4390,400 4650,400 4670,420 4670,740 4650,760 4265,760 4245,780 4245,935 4230,950 J36.2@4170,950 4120,950 4110,960 4110,1100 4145,1135 4545,1135 4775,1365 v1(4775,1550)
SPARE2_UC: J26.2 R173.2 U16.33 | length 2586.6
  Layer 1 - Top Layer w8: v1(4370,150) R173.2@4370,191.38 ; v1(4800,1515) 4800,1560 4942.36,1702.36 U16.33@4995.67,1702.36
  Layer 8 - Bottom Layer w8: v1(4370,150) 4370,290 4460,380 4665,380 4690,405 4690,760 4670,780 4490,780 4470,800 4470,930 4450,950 J26.2@4395,950 4345,950 4330,965 4330,1095 4350,1115 4550,1115 4800,1365 v1(4800,1515)
SPARE3_UC: C80.1 R141.1 S2.1 U16.32 | length 2131.9
  Layer 1 - Top Layer w8: v1(4875,1550) 4875,1605 4946.77,1676.77 U16.32@4995.67,1676.77 ; v1(5170,325) 5170,288.62 R141.1@5173.62,285 C80.1@5173.62,245 5173.62,166.38 5185,155 S2.1@5257.68,155
  Layer 8 - Bottom Layer w8: v1(4875,1550) 4875,1355 4750,1230 4750,357.76 4782.76,325 v1(5170,325)
SPARE4_UC: J39.2 R118.2 U16.31 | length 2087.1
  Layer 1 - Top Layer w8: v1(4460,150) R118.2@4460,191.38 ; v1(4825,1460) 4900,1535 4900,1600 4951.18,1651.18 U16.31@4995.67,1651.18
  Layer 8 - Bottom Layer w8: v1(4460,150) 4460,290 4530,360 4690,360 4710,380 4710,930 4690,950 J39.2@4620,950 4570,950 4550,970 4550,1090 4825,1365 v1(4825,1460)
SPI_CLK_OV1: J25.7 J31.5 J32.5 R63.2 R71.1 U10.6 | length 8028.4
  Layer 1 - Top Layer w8: J31.5@6450,2950 6500,3000 6580,3000 6620,3040 6620,3730 J32.5@6550,3800
  Layer 1 - Top Layer w10: v1(2950,2425) U10.6@3074.68,2425 R63.2@3151.38,2425
  Layer 6 - Signal w8: v1(2950,2425) 2950,2520 3145,2715 5895,2715 v1(5960,2780)
  Layer 8 - Bottom Layer w8: R71.1@1770,2591.38 1800,2591.38 1846.38,2545 2345,2545 2420,2620 2930,2620 2950,2600 v1(2950,2425) ; v1(5960,2780) 6105,2925 6105,3355 J32.5@6550,3800 ; J25.7@6450,2325 6500,2375 6575,2375 6600,2400 6600,2980 6580,3000 6530,3000 6510,2980 6480,2980 J31.5@6450,2950
SPI_CLK_OV2: J31.6 R93.2 R101.1 U14.6 | length 6303.3
  Layer 1 - Top Layer w10: v1(2935,3380) U14.6@3059.69,3380 R93.2@3146.38,3380 R93.2@3148.37,3380
  Layer 6 - Signal w8: v1(2935,3380) 2995,3380 3160,3545 3383.28,3545 3803.28,3125 5900,3125 v1(5945,3170)
  Layer 8 - Bottom Layer w8: R101.1@1728.62,3765 1728.62,3783.62 1740,3795 1795,3795 1955,3635 2270,3635 2335,3570 2915,3570 2935,3550 v1(2935,3380) ; v1(5945,3170) 5850,3075 5850,2720 5890,2680 6065,2680 6280,2895 6495,2895 J31.6@6550,2950
SPI_CS_OV1: J32.6 J40.1 R59.1 R73.1 U10.1 | length 8540.2
  Layer 1 - Top Layer w8: J40.1@6550,1700 6395,1700 6235,1860 6235,3790 6345,3900 J32.6@6550,3900
  Layer 1 - Top Layer w10: R59.1@2713,2525 U10.1@2785.31,2525 2785.31,2584.69 v1(2785,2585)
  Layer 6 - Signal w8: v1@2785.31,2585 2985,2585 3134,2734 5869,2734 v1(5915,2780)
  Layer 8 - Bottom Layer w8: R73.1@1725,2591.38 1725,2540 1740,2525 2360,2525 2420,2585 v1(2785,2585) ; v1(5915,2780) 6080,2945 6080,3430 J32.6@6550,3900
SPI_CS_OV2: J32.7 J40.3 R89.1 R103.1 U14.1 | length 8359.1
  Layer 1 - Top Layer w8: J40.3@6550,1900 6385,1900 6255,2030 6255,3760 6345,3850 6590,3850 6610,3870 6610,3940 J32.7@6550,4000
  Layer 1 - Top Layer w10: R89.1@2690,3480 U14.1@2770.32,3480 2820.51,3480 ; 2820.51,3485.51 v1(2820.51,3540)
  Layer 6 - Signal w8: v1(2820.51,3540) 2845.51,3565 3394.71,3565 3814.71,3145 5875,3145 v1(5900,3170)
  Layer 8 - Bottom Layer w8: R103.1@1728.62,3720 1840,3720 1945,3615 2255,3615 2330,3540 v1(2820.51,3540) ; v1(5900,3170) 5900,3350 J32.7@6550,4000
SPI_MISO_OV1: J25.5 J31.1 J32.3 R69.1 U10.2 | length 7276.8
  Layer 1 - Top Layer w8: R69.1@1725,2591.38 1725,2505 1755,2475 v1(2905,2475) ; J31.1@6450,3150 6450,3500 J32.3@6550,3600
  Layer 6 - Signal w8: v1(2905,2475) 2905,2335 2935,2305 3030,2305 3055,2330 3055,2565 3165,2675 5945,2675 v1(6050,2780) ; J25.5@6450,2425 6375,2425 6355,2445 6355,3055 J31.1@6450,3150
  Layer 8 - Bottom Layer w8: v1(6050,2780) 6155,2885 6155,3205 J32.3@6550,3600
SPI_MISO_OV2: J31.2 R99.1 U14.2 | length 6280.8
  Layer 1 - Top Layer w8: R99.1@1728.62,3720 2240,3720 2530,3430 U14.2@2770.32,3430 v1(2890,3430)
  Layer 6 - Signal w8: v1(2890,3430) 2890,3300 2921.84,3268.16 3118.16,3268.16 3145,3295 3145,3415 3235,3505 3370,3505 3790,3085 5950,3085 v1(6035,3170)
  Layer 8 - Bottom Layer w8: v1(6035,3170) 5890,3025 5890,2745 5915,2720 6035,2720 6415,3100 6500,3100 J31.2@6550,3150
SPI_MOSI_OV1: J25.8 J31.3 J32.4 R70.1 U10.5 | length 7901.8
  Layer 1 - Top Layer w8: R70.1@1590,2591.38 1590,2490 1625,2455 2130,2455 2310,2275 2850,2275 2950,2375 v1(3024.49,2375) U10.5@3074.68,2375 ; J31.3@6450,3050 6500,3100 6580,3100 6600,3120 6600,3650 J32.4@6550,3700
  Layer 6 - Signal w8: v1(3024.49,2375) 3024.49,2564.48 3155,2695 5920,2695 v1(6005,2780)
  Layer 8 - Bottom Layer w8: v1(6005,2780) 6130,2905 6130,3280 J32.4@6550,3700 ; J31.3@6450,3050 6480,3080 6510,3080 6530,3100 6580,3100 6620,3060 6620,2345 6600,2325 J25.8@6550,2325
SPI_MOSI_OV2: J31.4 R100.1 U14.5 | length 6178.9
  Layer 1 - Top Layer w8: R100.1@1728.62,3585 2210,3585 2565,3230 2830,3230 2930,3330 U14.5@3059.69,3330 v1(3059.68,3290.52)
  Layer 6 - Signal w8: v1(3059.68,3290.52) 3105.52,3290.52 3125,3310 3125,3425 3225,3525 3375,3525 3795,3105 5925,3105 v1(5990,3170)
  Layer 8 - Bottom Layer w8: v1(5990,3170) 5870,3050 5870,2735 5905,2700 6050,2700 6350,3000 6500,3000 J31.4@6550,3050
SYS_CLK_25MHZ: R46.2 R80.1 R110.1 | length 5843.7
  Layer 1 - Top Layer w8: R46.2@1054.82,2670 v1(1095,2670)
  Layer 6 - Signal w9.5: v1(1830,3800) 2115,3800 2245,3670 2245,3305 2135,3195 2135,3060 2190,3005 v1(2345,3005)
  Layer 8 - Bottom Layer w8: v1(1095,2670) 1300,2465 2345,2465 2535,2275 2945,2275 2985,2315 2985,2605 2945,2645 2425,2645 2365,2705 2365,2985 v1(2345,3005)
  Layer 8 - Bottom Layer w9.5: R110.1@1320,4213.62 1320,4270 1380,4330 1580,4330 1650,4260 1650,3860 1685,3825 1805,3825 v1(1830,3800) ; R80.1@2273.62,3005 v1(2345,3005)
SYS_CLK_OV1: R79.1 R80.2 R81.2 U8.E1 | length 427.4
  Layer 8 - Bottom Layer w8: U8.E1@1912.8,2959.84 1912.8,2947.2 1970.69,2889.31 2034.31,2889.31 2100,2955 R81.2@2226.38,2955 R80.2@2226.38,3005
SYS_CLK_OV2: R109.1 R110.2 R111.2 U12.E1 | length 382
  Layer 8 - Bottom Layer w8: R110.2@1320,4166.38 R111.2@1365,4166.38 1365,4100 1435,4030 R109.1@1441.38,4030 1441.38,3972.64 1374.04,3905.3 U12.E1@1361.4,3905.3
TDIO1: C155.1 J23.3 R116.1 R156.1 S1.1 U16.7 | length 5092.8
  Layer 1 - Top Layer w8: S1.1@4592.32,155 4635,155 4651.38,171.38 C155.1@4651.38,245 R116.1@4651.38,285 ; R156.1@4606.5,1675 R156.1@4606.5,1676.77 ; R116.1@4650,286.38 v1(4650,325) ; v1(4760,1676.77) U16.7@4704.33,1676.77 R156.1@4606.5,1676.77 ; J23.3@6608,1455 5590,1455 5565,1480 5565,2015 5400,2180 4930,2180 4790,2040 4790,1930 4760,1900 4670,1900 4640,1930 4525,1930 4510,1915 4510,1750 4535.6,1724.4 4595.6,1724.4 4606.5,1713.5 R156.1@4606.5,1676.77
  Layer 8 - Bottom Layer w8: v1(4650,325) 4690,325 4730,365 4730,1240 4850,1360 4850,1586.77 v1(4760,1676.77)
V_CAM: D8.1 R32.2 R33.2 R34.2 R35.2 TP7.1 U4.5 U4.6 U4.7 | length 390.4
  Layer 1 - Top Layer w20: D8.1@3550,6535 v1(3550,6565)
  Layer 8 - Bottom Layer w20: v1(3550,6565) 3550,6240 3575,6215
  other v1: 3630,6175 3670,6175 3630,6215 3670,6215
V_CAM1: C3.1 C4.1 L1.2 R32.1 TP1.1 | length 6303.6
  Layer 1 - Top Layer w20: L1.2@92.44,4855 92.44,4951.06 C3.1@96.38,4955 v1(96.38,5005) ; R32.1@3710,6108.5 v1(3710,6065) 3780,5995 5040,5995 5100,6055 TP1.1@5100,6300
  Layer 8 - Bottom Layer w20: v1(96.38,5005) 96.38,5071.38 145,5120 3325,5120 3475,5270 3475,5830 v1(3710,6065)
V_CAM2: C7.1 C8.1 L2.2 R33.1 TP2.1 | length 6877.4
  Layer 1 - Top Layer w20: L2.2@92.44,3925 C8.1@92.44,3975 96.38,3978.94 C7.1@96.38,4025 96.38,4027.5 95,4028.88 v1(95,4105) ; R33.1@3765,6108.5 v1(3765,6065) 3800,6030 4850,6030 4900,6080 TP2.1@4900,6300
  Layer 8 - Bottom Layer w20: v1(95,4105) 95,4171.38 143.62,4220 515,4220 540,4245 540,4955 670,5085 3339.5,5085 3510,5255.5 3510,5810 v1(3765,6065)
V_CAM3: C17.1 C18.1 L9.2 R34.1 TP3.1 | length 7551.7
  Layer 1 - Top Layer w20: L9.2@87.44,3000 C18.1@87.44,3050 91.38,3053.94 C17.1@91.38,3102.5 90,3103.88 v1(90,3155) ; R34.1@3820,6108.5 v1(3820,6065) 4665,6065 4700,6100 TP3.1@4700,6300
  Layer 8 - Bottom Layer w20: v1(90,3155) 90,3221.38 138.62,3270 550,3270 580,3300 580,4940 690,5050 3353.99,5050 3545,5241.01 3545,5790 v1(3820,6065)
V_CAM4: C21.1 C22.1 L10.2 R35.1 TP4.1 | length 8228.4
  Layer 1 - Top Layer w20: L10.2@92.44,2080 C22.1@92.44,2130 96.38,2133.94 C21.1@96.38,2180 96.38,2182.5 95,2183.88 v1(95,2255) ; R35.1@3875,6108.5 v1(3918.5,6108.5) 4458.5,6108.5 4500,6150 TP4.1@4500,6300
  Layer 8 - Bottom Layer w20: v1(95,2255) 95,2321.38 143.62,2370 590,2370 620,2400 620,4930 705,5015 3368.49,5015 3580,5226.51 3580,5770 v1(3918.5,6108.5)
V_MAIN: D7.2 J6.3 J8.3 R24.2 | length 561.9
  Layer 1 - Top Layer w20: D7.2@3460,6535 v1(3460,6565)
  Layer 8 - Bottom Layer w20: J6.3@3150,6305 3150,6420 3195,6465 3440,6465 3460,6485 v1(3460,6565)
VDD18_P0: C69.1 C70.1 C71.1 C76.1 C77.1 C84.1 C85.1 C90.1 C91.1 L23.2 U1.1 U1.2 U1.47 U1.48 | length 1355.2
  Layer 1 - Top Layer w8: v1(985,2905) 997.05,2917.05 U1.2@997.05,2944.27 ; v1(985,3325) 997.05,3312.95 U1.47@997.05,3290.73
  Layer 1 - Top Layer w15: C85.1@950,2898.62 950,2935 959.27,2944.27 U1.1@974,2944.27 ; C71.1@950,3336.38 950,3300 959.27,3290.73 U1.48@974,3290.73
  Layer 1 - Top Layer w20: v1(855,2905) 893.5,2905 C84.1@895,2906.5 902.87,2898.62 C85.1@950,2898.62 978.62,2898.62 v1(985,2905) ; v1(855,3330) 893.5,3330 C70.1@895,3328.5 902.87,3336.38 C71.1@950,3336.38 973.62,3336.38 v1(985,3325)
  Layer 6 - Signal w30: v1(855,2905) 785,2975 785,3260 v1(855,3330)
  Layer 8 - Bottom Layer w20: L23.2@845,3448.5 814,3417.5 814,3351 835,3330 v1(855,3330) 861.38,3336.38 C69.1@895,3336.38 ; C77.1@950,3336.38 961.38,3325 v1(985,3325) 990,3330 1013.5,3330 C76.1@1020,3336.5 ; v1(985,2905) 987,2907 1025.62,2907 C91.1@1030,2911.38 1042.87,2898.5 C90.1@1080,2898.5
VDD18A: C56.1 C57.1 C58.1 L21.2 U1.32 | length 315.2
  Layer 1 - Top Layer w8: U1.32@1298.23,3265.14 1365.14,3265.14 v1(1375,3275)
  Layer 8 - Bottom Layer w20: C57.1@1336.5,3225 1335,3226.5 1335,3268.62 C58.1@1328.62,3275 v1(1375,3275) 1445,3275 1460,3260 1491.5,3260 L21.2@1500,3268.5
VDDCSI_1V1: C100.1 C101.1 C102.1 C103.1 L28.2 U1.21 U1.33 | length 731
  Layer 1 - Top Layer w8: U1.21@1298.23,3048.6 1351.4,3048.6 v1(1370,3030)
  Layer 1 - Top Layer w15: U1.33@1276,3290.73 1305.73,3290.73 1315,3300 C103.1@1315,3336.38
  Layer 1 - Top Layer w20: C103.1@1315,3336.38 1362.13,3336.38 C101.1@1370,3328.5 1371.5,3330 v1(1410,3330)
  Layer 6 - Signal w30: v1(1370,3030) 1370,3170 1430,3230 1430,3310 v1(1410,3330)
  Layer 8 - Bottom Layer w20: C100.1@1315,3336.38 1362.13,3336.38 L28.2@1370,3328.5 1408.5,3328.5 v1(1410,3330) ; C102.1@1328.62,3030 v1(1370,3030)
VDDFPD18: C60.1 C61.1 C62.1 C63.1 C64.1 C65.1 C66.1 L22.2 U1.49 U1.55 U1.58 U1.64 | length 1217.6
  Layer 1 - Top Layer w8: v1(861.08,3265.14) U1.49@951.77,3265.14 ; v1(880,2950) 899.86,2969.86 U1.64@951.77,2969.86 ; v1(890,3087.97) U1.58@951.77,3087.97 ; v1(890,3147.03) U1.55@951.77,3147.03
  Layer 6 - Signal w30: v1(861.08,3265.14) 929.86,3265.14 945,3250 945,3168.37 923.66,3147.03 v1(890,3147.03) v1(890,3087.97) 925,3052.97 925,3015 880,2970 v1(880,2950)
  Layer 8 - Bottom Layer w20: L22.2@765,2961.5 771.5,2955 875,2955 v1(880,2950) 890,2940 C64.1@926.38,2940 ; v1(861.08,3265.14) 902.42,3265.14 C62.1@903.5,3266.22 ; v1(890,3087.97) 892.97,3085 C65.1@926.38,3085 ; C60.1@915,2845 915,2900 926.38,2911.38 C64.1@926.38,2940 ; C64.1@926.38,2941 C64.1@926.38,2940 ; C66.1@926.38,3130 900,3130 890,3140 v1(890,3147.03) 890,3165 900,3175 C63.1@926.38,3175
VDDFPD_1V1: C111.1 C112.1 C113.1 C114.1 L30.2 U1.52 U1.61 | length 677.2
  Layer 1 - Top Layer w8: v1(880,3028.92) U1.61@951.77,3028.92 ; v1(890,3206.08) U1.52@951.77,3206.08
  Layer 6 - Signal w30: v1@880,3030 838.92,3071.08 838.92,3181.49 863.51,3206.08 v1(890,3206.08)
  Layer 8 - Bottom Layer w20: C111.1@773.62,3260 773.62,3217.87 L30.2@781.5,3210 ; L30.2@781.5,3215 790.41,3206.08 v1(890,3206.08) 903.92,3220 C114.1@926.38,3220 ; v1(880,3028.92) 891.08,3040 C113.1@926.38,3040 922,3035.62 922,2998.5 C112.1@913.5,2990
VDDL_1V1: C94.1 C95.1 C96.1 C97.1 L27.2 U1.13 U1.44 | length 951
  Layer 1 - Top Layer w8: U1.44@1056.1,3290.73 1056.1,3321.1 v1(1060,3325) ; U1.13@1213.58,2944.27 1213.58,2896.42 v1(1220,2890)
  Layer 6 - Signal w30: v1(1060,3325) 1175,3325 1275,3225 1275,2945 v1(1220,2890)
  Layer 8 - Bottom Layer w20: v1(1060,3325) 1070,3335 1098.5,3335 C95.1@1100,3336.5 1137.13,3336.5 C94.1@1150,3323.62 1197.13,3323.62 L27.2@1203.5,3330 ; C96.1@1185,2911.38 1206.38,2890 v1(1220,2890) 1233.62,2890 C97.1@1255,2911.38
VIN1A_CLK: J29.48 R198.1 | length 92.3
  Layer 8 - Bottom Layer w5: J29.48@4254.91,3900.89 4254.91,3808.71 R198.1@4255,3808.62
VIN1A_D00: J29.40 R190.1 | length 88.7
  Layer 8 - Bottom Layer w5: R190.1@4535,3813.62 4538.38,3817 J29.40@4538.38,3900.89
VIN1A_D01: J29.41 R191.2 | length 197
  Layer 8 - Bottom Layer w5: J29.41@4349.4,4143.8 R191.2@4349.4,4340.78
VIN1A_D02: J29.42 R192.1 | length 196.7
  Layer 8 - Bottom Layer w5: R192.1@4349.4,3704.22 J29.42@4349.4,3900.89
VIN1A_D03: J29.43 R193.2 | length 92.6
  Layer 8 - Bottom Layer w5: J29.43@4317.9,4143.8 R193.2@4317.9,4236.38
VIN1A_D04: J29.44 R194.1 | length 93.1
  Layer 8 - Bottom Layer w5: J29.44@4317.9,3900.89 4317.9,3810.72 R194.1@4320,3808.62
VIN1A_D05: J29.45 R195.2 | length 197.6
  Layer 8 - Bottom Layer w5: J29.45@4286.41,4143.8 R195.2@4286.41,4341.38
VIN1A_D06: J29.46 R196.1 | length 205.9
  Layer 8 - Bottom Layer w5: R196.1@4286.41,3695.03 J29.46@4286.41,3900.89
VIN1A_D07: J29.47 R197.2 | length 94.6
  Layer 8 - Bottom Layer w5: R197.2@4250,4236.38 4254.91,4231.47 J29.47@4254.91,4143.8
VIN1A_D08: J29.68 R206.1 | length 94.4
  Layer 8 - Bottom Layer w5: J29.68@3939.95,3900.89 3939.95,3813.67 R206.1@3945,3808.62
VIN1A_D09: J29.67 R205.2 | length 87.5
  Layer 8 - Bottom Layer w5: J29.67@3939.95,4143.8 R205.2@3939.95,4231.33
VIN1A_D10: J29.70 R208.1 | length 197.9
  Layer 8 - Bottom Layer w5: J29.70@3908.45,3900.89 3908.45,3705.17 R208.1@3910,3703.62
VIN1A_D11: J29.69 R207.2 | length 196
  Layer 8 - Bottom Layer w5: J29.69@3908.45,4143.8 R207.2@3908.45,4339.83
VIN1A_D12: J29.72 R210.1 | length 89.2
  Layer 8 - Bottom Layer w5: R210.1@3876.96,3811.66 J29.72@3876.96,3900.89
VIN1A_D13: J29.71 R209.2 | length 89.5
  Layer 8 - Bottom Layer w5: J29.71@3876.96,4143.8 R209.2@3876.96,4233.34
VIN1A_D14: J29.74 R212.1 | length 196.8
  Layer 8 - Bottom Layer w5: R212.1@3845.46,3704.08 J29.74@3845.46,3900.89
VIN1A_D15: J29.73 R211.2 | length 197.6
  Layer 8 - Bottom Layer w5: J29.73@3845.46,4143.8 R211.2@3845.46,4341.38
VIN1A_DE0: J29.25 R151.2 | length 91.4
  Layer 8 - Bottom Layer w5: J29.25@4758.85,4143.8 R151.2@4758.85,4235.23
VIN1A_FLD0_0: J29.85 R221.2 | length 193.6
  Layer 8 - Bottom Layer w5: J29.85@3499.01,4143.8 R221.2@3499.01,4337.37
